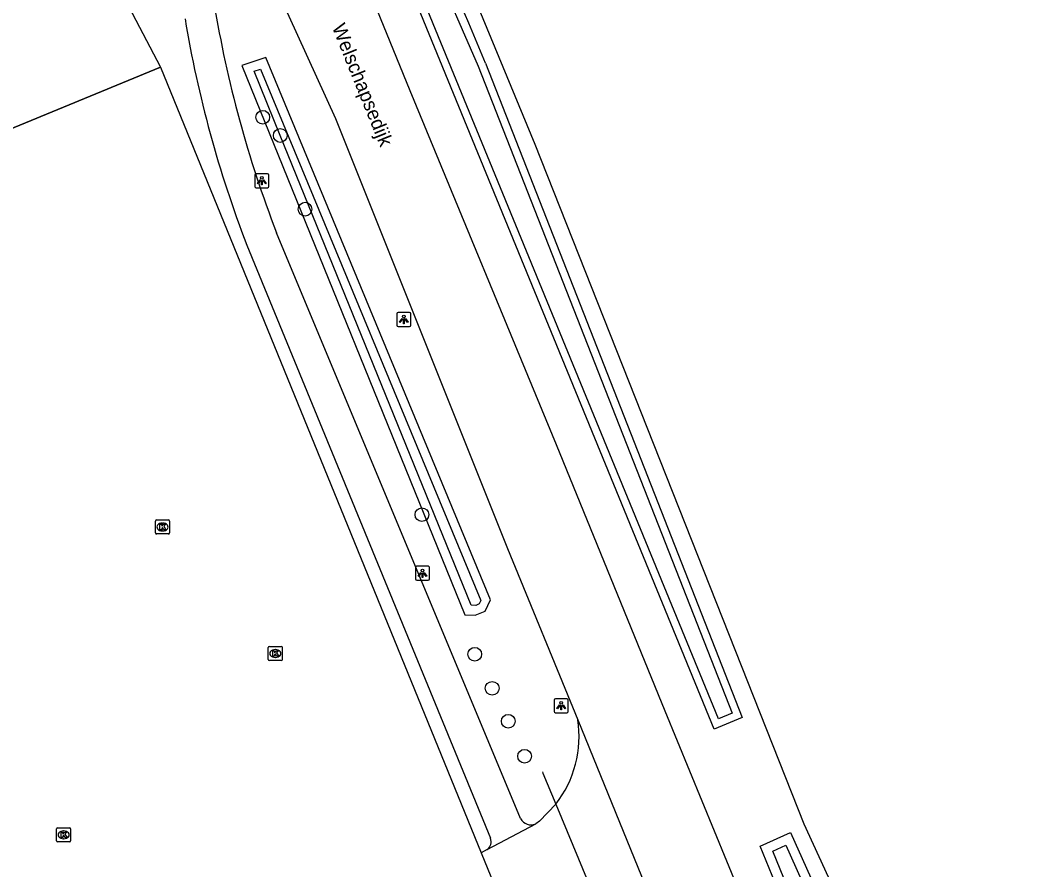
# Model space of a CAD drawing. Extents: x 156061 to 157804, y 383451 to 385640.
# Drawn here: x 157555.9 to 157628.5, y 383825.3 to 383885.9 of the extents above; entities that cross this region are included whole.
import ezdxf

# ---------------------------------------------------------------- set-up
doc = ezdxf.new("R2010")
doc.units = 0
for name, color, linetype in [('IMGEO_Boom', 7, 'Continuous'), ('IMGEO_Bouwland', 7, 'Continuous'), ('IMGEO_Duiker', 7, 'Continuous'), ('IMGEO_Fietspad_gesloten', 7, 'Continuous'), ('IMGEO_Grasland_overig', 7, 'Continuous'), ('IMGEO_Groenvoorziening', 7, 'Continuous'), ('IMGEO_Hek', 7, 'Continuous'), ('IMGEO_Kolk', 7, 'Continuous'), ('IMGEO_Lichtpunt', 7, 'Continuous'), ('IMGEO_Openbare_ruimte_label', 7, 'Continuous'), ('IMGEO_Rijbaan_lokaal_gesloten', 7, 'Continuous'), ('IMGEO_Waterloop', 7, 'Continuous')]:
    doc.layers.add(name, color=color, linetype=linetype)

msp = doc.modelspace()

# ---------------------------------------------------------------- linework, layer by layer
at = {"layer": 'IMGEO_Boom'}
for centre in [(157573.23, 383879.012), (157574.474, 383877.713), (157576.243, 383872.456), (157584.585, 383850.666), (157588.355, 383840.711), (157589.594, 383838.279), (157590.74, 383835.926), (157591.907, 383833.435)]:
    msp.add_circle(centre, 0.489, dxfattribs=at)
at = {"layer": 'IMGEO_Bouwland'}
msp.add_lwpolyline([(157702.798, 383849.357), (157707.546, 383840.384), (157700.202, 383834.337), (157695.919, 383830.811), (157693.54, 383829.055), (157691.043, 383827.496), (157689.841, 383826.746), (157683.073, 383823.26), (157676.592, 383820.429), (157634.606, 383803.387), (157626.262, 383803.732), (157620.267, 383810.258), (157611.861, 383828.593), (157592.659, 383877.063), (157588.089, 383888.129), (157579.364, 383907.864), (157571.61, 383923.119), (157569.269, 383927.726), (157568.674, 383928.38)], dxfattribs=at)
at = {"layer": 'IMGEO_Duiker'}
msp.add_lwpolyline([(157593.175, 383832.32), (157593.217, 383832.219), (157594.135, 383830.012), (157597.662, 383821.536), (157598.502, 383819.516), (157598.62, 383819.234)], dxfattribs=at)
at = {"layer": 'IMGEO_Fietspad_gesloten'}
for points in [[(157591.619, 383828.994), (157574.219, 383870.769)], [(157572.089, 383869.901), (157589.47, 383827.582)]]:
    msp.add_lwpolyline(points, dxfattribs=at)
for centre, radius, start, end in [((157650.226, 383900.279), 81.535, 189.27321, 201.21866), ((157649.02, 383899.57), 82.454, 189.44953, 201.08955), ((157592.361, 383829.374), 0.834, 207.15129, 294.53155), ((157588.84, 383827.335), 0.676, 305.71255, 21.39149)]:
    msp.add_arc(centre, radius, start, end, dxfattribs=at)
at = {"layer": 'IMGEO_Grasland_overig'}
for points in [[(157554.173, 383911.134), (157562.422, 383889.314), (157565.924, 383882.594)], [(157565.924, 383882.594), (157500, 383855.42), (157463.791, 383840.494)]]:
    msp.add_lwpolyline(points, dxfattribs=at)
at = {"layer": 'IMGEO_Groenvoorziening'}
for points in [[(157589.126, 383882.867), (157607.436, 383836.202), (157605.427, 383835.371), (157584.115, 383887.329), (157576.317, 383905.276)], [(157573.438, 383883.276), (157571.725, 383882.697), (157587.647, 383843.51), (157588.375, 383843.5), (157589.085, 383843.789), (157589.476, 383844.598), (157573.438, 383883.276)], [(157565.924, 383882.594), (157588.82, 383826.546)], [(157614.914, 383811.856), (157608.724, 383827.011), (157610.885, 383827.994), (157618.869, 383810.192)]]:
    msp.add_lwpolyline(points, dxfattribs=at)
msp.add_arc((157159.809, 383704.268), 464.985, 22.5876, 28.70083, dxfattribs=at)
at = {"layer": 'IMGEO_Hek'}
for points in [[(157500, 383855.42), (157565.924, 383882.594)], [(157565.924, 383882.594), (157588.82, 383826.546)], [(157588.82, 383826.546), (157591.436, 383820.144)]]:
    msp.add_lwpolyline(points, dxfattribs=at)
at = {"layer": 'IMGEO_Kolk'}
for p, q in [((157565.576, 383849.361), (157565.576, 383850.213)), ((157565.651, 383850.287), (157566.503, 383850.287)), ((157566.577, 383850.213), (157566.577, 383849.361)), ((157566.087, 383849.507), (157566.062, 383849.507)), ((157566.064, 383850.067), (157566.089, 383850.067)), ((157566.503, 383849.287), (157565.651, 383849.287)), ((157573.624, 383840.338), (157573.624, 383841.19)), ((157573.699, 383841.264), (157574.551, 383841.264)), ((157574.112, 383841.044), (157574.137, 383841.044)), ((157574.625, 383841.19), (157574.625, 383840.338)), ((157574.551, 383840.264), (157573.699, 383840.264)), ((157574.135, 383840.484), (157574.11, 383840.484)), ((157558.523, 383827.403), (157558.523, 383828.255)), ((157558.598, 383828.329), (157559.45, 383828.329)), ((157559.011, 383828.109), (157559.036, 383828.109)), ((157559.524, 383828.255), (157559.524, 383827.403)), ((157559.45, 383827.329), (157558.598, 383827.329)), ((157559.034, 383827.549), (157559.009, 383827.549))]:
    msp.add_line(p, q, dxfattribs=at)
for points in [[(157565.576, 383849.361), (157565.576, 383850.213)], [(157565.651, 383850.287), (157566.503, 383850.287)], [(157566.577, 383850.213), (157566.577, 383849.361)], [(157565.897, 383849.987), (157566.02, 383849.987), (157566.02, 383849.836), (157566.15, 383849.987), (157566.314, 383849.987), (157566.168, 383849.836), (157566.321, 383849.587), (157566.169, 383849.587), (157566.084, 383849.751), (157566.02, 383849.684), (157566.02, 383849.587), (157565.897, 383849.587), (157565.897, 383849.987)], [(157566.503, 383849.287), (157565.651, 383849.287)], [(157573.624, 383840.338), (157573.624, 383841.19)], [(157573.699, 383841.264), (157574.551, 383841.264)], [(157573.945, 383840.964), (157574.068, 383840.964), (157574.068, 383840.813), (157574.198, 383840.964), (157574.362, 383840.964), (157574.216, 383840.813), (157574.369, 383840.564), (157574.217, 383840.564), (157574.132, 383840.728), (157574.068, 383840.661), (157574.068, 383840.564), (157573.945, 383840.564), (157573.945, 383840.964)], [(157574.625, 383841.19), (157574.625, 383840.338)], [(157574.551, 383840.264), (157573.699, 383840.264)], [(157558.523, 383827.403), (157558.523, 383828.255)], [(157558.598, 383828.329), (157559.45, 383828.329)], [(157558.844, 383828.029), (157558.967, 383828.029), (157558.967, 383827.878), (157559.097, 383828.029), (157559.261, 383828.029), (157559.115, 383827.878), (157559.268, 383827.629), (157559.116, 383827.629), (157559.031, 383827.793), (157558.967, 383827.726), (157558.967, 383827.629), (157558.844, 383827.629), (157558.844, 383828.029)], [(157559.524, 383828.255), (157559.524, 383827.403)], [(157559.45, 383827.329), (157558.598, 383827.329)]]:
    msp.add_lwpolyline(points, dxfattribs=at)
for centre, start, end in [((157565.653, 383850.211), 91.55205, 178.44795), ((157565.653, 383850.211), 91.55205, 178.44795), ((157566.501, 383850.211), 1.55205, 88.44795), ((157566.501, 383850.211), 1.55205, 88.44795), ((157565.653, 383849.363), 181.55205, 268.44795), ((157565.653, 383849.363), 181.55205, 268.44795), ((157566.501, 383849.363), 271.55205, 358.44795), ((157566.501, 383849.363), 271.55205, 358.44795), ((157573.701, 383841.188), 91.55205, 178.44795), ((157573.701, 383841.188), 91.55205, 178.44795), ((157574.549, 383841.188), 1.55205, 88.44795), ((157574.549, 383841.188), 1.55205, 88.44795), ((157573.701, 383840.34), 181.55205, 268.44795), ((157573.701, 383840.34), 181.55205, 268.44795), ((157574.549, 383840.34), 271.55205, 358.44795), ((157574.549, 383840.34), 271.55205, 358.44795), ((157558.6, 383828.253), 91.55205, 178.44795), ((157558.6, 383828.253), 91.55205, 178.44795), ((157559.448, 383828.253), 1.55205, 88.44795), ((157559.448, 383828.253), 1.55205, 88.44795), ((157558.6, 383827.405), 181.55205, 268.44795), ((157558.6, 383827.405), 181.55205, 268.44795), ((157559.448, 383827.405), 271.55205, 358.44795), ((157559.448, 383827.405), 271.55205, 358.44795)]:
    msp.add_arc(centre, 0.0765, start, end, dxfattribs=at)
for centre, major_axis, ratio, start_param, end_param in [((157566.063, 383849.787), (-0.387, 0.002), 0.722429, 4.712389, 7.853982), ((157566.088, 383849.787), (-0.39, 0.002), 0.717154, 1.570796, 4.712389), ((157574.111, 383840.764), (-0.387, 0.002), 0.722429, 4.712389, 7.853982), ((157574.136, 383840.764), (-0.39, 0.002), 0.717154, 1.570796, 4.712389), ((157559.01, 383827.829), (-0.387, 0.002), 0.722429, 4.712389, 7.853982), ((157559.035, 383827.829), (-0.39, 0.002), 0.717154, 1.570796, 4.712389)]:
    msp.add_ellipse(centre, major_axis=major_axis, ratio=ratio, start_param=start_param, end_param=end_param, dxfattribs=at)
at = {"layer": 'IMGEO_Lichtpunt'}
for p, q in [((157572.666, 383874.889), (157572.666, 383874.082)), ((157572.666, 383874.889), (157572.666, 383874.082)), ((157573.568, 383874.984), (157572.76, 383874.984)), ((157573.568, 383874.984), (157572.76, 383874.984)), ((157573.662, 383874.082), (157573.662, 383874.889)), ((157573.662, 383874.082), (157573.662, 383874.889)), ((157572.76, 383873.988), (157573.568, 383873.988)), ((157572.76, 383873.988), (157573.568, 383873.988)), ((157582.789, 383864.994), (157582.789, 383864.187)), ((157582.789, 383864.994), (157582.789, 383864.187)), ((157583.691, 383865.089), (157582.883, 383865.089)), ((157583.691, 383865.089), (157582.883, 383865.089)), ((157583.785, 383864.187), (157583.785, 383864.994)), ((157583.785, 383864.187), (157583.785, 383864.994)), ((157582.883, 383864.093), (157583.691, 383864.093)), ((157582.883, 383864.093), (157583.691, 383864.093)), ((157584.121, 383846.886), (157584.121, 383846.079)), ((157584.121, 383846.886), (157584.121, 383846.079)), ((157585.023, 383846.981), (157584.215, 383846.981)), ((157585.023, 383846.981), (157584.215, 383846.981)), ((157585.117, 383846.079), (157585.117, 383846.886)), ((157585.117, 383846.079), (157585.117, 383846.886)), ((157584.215, 383845.985), (157585.023, 383845.985)), ((157584.215, 383845.985), (157585.023, 383845.985)), ((157594.024, 383837.442), (157594.024, 383836.635)), ((157594.024, 383837.442), (157594.024, 383836.635)), ((157594.926, 383837.537), (157594.118, 383837.537)), ((157594.926, 383837.537), (157594.118, 383837.537)), ((157595.02, 383836.635), (157595.02, 383837.442)), ((157595.02, 383836.635), (157595.02, 383837.442)), ((157594.118, 383836.541), (157594.926, 383836.541)), ((157594.118, 383836.541), (157594.926, 383836.541))]:
    msp.add_line(p, q, dxfattribs=at)
for points in [[(157573.04, 383874.553), (157573.079, 383874.525), (157572.891, 383874.263), (157572.853, 383874.29), (157573.04, 383874.553)], [(157573.142, 383874.505), (157573.189, 383874.505), (157573.189, 383874.183), (157573.142, 383874.183), (157573.142, 383874.505)], [(157573.252, 383874.525), (157573.29, 383874.552), (157573.477, 383874.29), (157573.438, 383874.262), (157573.252, 383874.525)], [(157583.163, 383864.658), (157583.202, 383864.63), (157583.014, 383864.368), (157582.976, 383864.395), (157583.163, 383864.658)], [(157583.265, 383864.61), (157583.312, 383864.61), (157583.312, 383864.288), (157583.265, 383864.288), (157583.265, 383864.61)], [(157583.375, 383864.63), (157583.413, 383864.657), (157583.6, 383864.395), (157583.561, 383864.367), (157583.375, 383864.63)], [(157584.495, 383846.55), (157584.534, 383846.522), (157584.346, 383846.26), (157584.308, 383846.287), (157584.495, 383846.55)], [(157584.707, 383846.522), (157584.745, 383846.549), (157584.932, 383846.287), (157584.893, 383846.259), (157584.707, 383846.522)], [(157584.597, 383846.502), (157584.644, 383846.502), (157584.644, 383846.18), (157584.597, 383846.18), (157584.597, 383846.502)], [(157594.398, 383837.106), (157594.437, 383837.078), (157594.249, 383836.816), (157594.211, 383836.843), (157594.398, 383837.106)], [(157594.61, 383837.078), (157594.648, 383837.105), (157594.835, 383836.843), (157594.796, 383836.815), (157594.61, 383837.078)], [(157594.5, 383837.058), (157594.547, 383837.058), (157594.547, 383836.736), (157594.5, 383836.736), (157594.5, 383837.058)]]:
    msp.add_lwpolyline(points, dxfattribs=at)
for centre in [(157573.165, 383874.687), (157583.288, 383864.792), (157584.62, 383846.684), (157594.523, 383837.24)]:
    msp.add_circle(centre, 0.0994, dxfattribs=at)
for centre, start, end in [((157572.76, 383874.889), 90, 180), ((157572.76, 383874.889), 90, 180), ((157573.568, 383874.889), 0, 90), ((157573.568, 383874.889), 0, 90), ((157572.76, 383874.082), 180, 270), ((157572.76, 383874.082), 180, 270), ((157573.568, 383874.082), 270, 0), ((157573.568, 383874.082), 270, 360), ((157582.883, 383864.994), 90, 180), ((157582.883, 383864.994), 90, 180), ((157583.691, 383864.994), 0, 90), ((157583.691, 383864.994), 0, 90), ((157582.883, 383864.187), 180, 270), ((157582.883, 383864.187), 180, 270), ((157583.691, 383864.187), 270, 0), ((157583.691, 383864.187), 270, 360), ((157584.215, 383846.886), 90, 180), ((157584.215, 383846.886), 90, 180), ((157585.023, 383846.886), 0, 90), ((157585.023, 383846.886), 0, 90), ((157584.215, 383846.079), 180, 270), ((157584.215, 383846.079), 180, 270), ((157585.023, 383846.079), 270, 0), ((157585.023, 383846.079), 270, 360), ((157594.118, 383837.442), 90, 180), ((157594.118, 383837.442), 90, 180), ((157594.926, 383837.442), 0, 90), ((157594.926, 383837.442), 0, 90), ((157594.118, 383836.635), 180, 270), ((157594.118, 383836.635), 180, 270), ((157594.926, 383836.635), 270, 0), ((157594.926, 383836.635), 270, 360)]:
    msp.add_arc(centre, 0.0946, start, end, dxfattribs=at)
at = {"layer": 'IMGEO_Rijbaan_lokaal_gesloten'}
for points in [[(157612.747, 383810.251), (157610.744, 383815.241), (157601.935, 383836.642), (157594.173, 383855.636), (157583.743, 383880.908), (157580.203, 383889.6), (157580.13, 383890.352)], [(157574.359, 383887.856), (157578.419, 383878.917), (157590.677, 383848.249), (157595.701, 383836.038)], [(157595.701, 383836.038), (157602.956, 383818.231)], [(157594.135, 383830.012), (157592.966, 383828.799), (157592.707, 383828.616)], [(157589.235, 383826.786), (157592.707, 383828.616)], [(157589.235, 383826.786), (157588.82, 383826.546)], [(157588.82, 383826.546), (157591.436, 383820.144)]]:
    msp.add_lwpolyline(points, dxfattribs=at)
msp.add_arc((157587.907, 383834.847), 7.885, 322.17817, 8.68693, dxfattribs=at)
at = {"layer": 'IMGEO_Waterloop'}
for points in [[(157566.057, 383926.043), (157567.443, 383926.809), (157575.014, 383912.342), (157582.071, 383897.619), (157588.606, 383882.657), (157606.713, 383836.509), (157605.732, 383836.104), (157584.631, 383887.547), (157576.827, 383905.507), (157573.431, 383912.453), (157569.84, 383919.3), (157566.057, 383926.043)], [(157588.09, 383844.201), (157574.474, 383877.713), (157572.615, 383882.289), (157573.058, 383882.439), (157588.776, 383844.536), (157588.662, 383844.296), (157588.422, 383844.184), (157588.09, 383844.201)], [(157615.568, 383812.076), (157609.612, 383826.658), (157610.54, 383827.081), (157618.255, 383809.88)]]:
    msp.add_lwpolyline(points, dxfattribs=at)

# ---------------------------------------------------------------- texts
at = {"layer": 'IMGEO_Openbare_ruimte_label'}
msp.add_text('Welschapsedijk', height=1, rotation=291.97171, dxfattribs=at).set_placement((157578.148, 383885.449))

doc.saveas('drawing.dxf')
